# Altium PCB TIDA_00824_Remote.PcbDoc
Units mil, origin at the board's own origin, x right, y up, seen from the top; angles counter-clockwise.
Board outline 140 x 108 mil, 2 copper layers (Top Layer, Bottom Layer), stack 62 mil thick; 1 components, 0 nets, 4 pads, 7 vias.
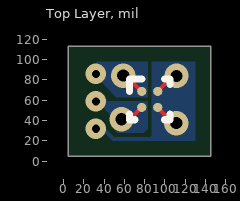
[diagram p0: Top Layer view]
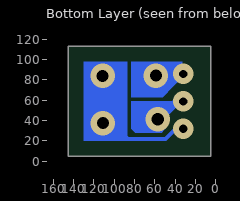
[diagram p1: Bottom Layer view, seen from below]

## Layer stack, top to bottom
Top Layer: signal copper 1.4
Dielectric: core 59.2, FR-4, Dk 4.8
Bottom Layer: signal copper 1.4

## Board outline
5,5 5,113 145,113 145,5

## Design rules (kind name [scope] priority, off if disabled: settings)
AcuteAngle [All] p1: minimum=4.50000000000000E+0001 checktracksonly=FALSE
AssemblyTestPointUsage [All] p1: valid=2
Clearance Clearance_BoardEdge_MountingHoles [OnCopper and InComponentClass('Mounting Holes') vs IsKeepOut] p1: gap=40
Clearance Clearance_BoardEdge_Poly [OnCopper and InPoly vs IsKeepOut] p2: gap=25
Clearance Clearance_BoardEdge [OnCopper and Not InComponentClass('Logo') and not InComponentClass('FiducialMark') and not InRegion(1000,500,4000,800) and Not IsKeepout vs IsKeepOut] p3: gap=75
Clearance Clearance_Poly [InPolygon] p4: gap=25
Clearance [All] p5: gap=7.87
ComponentClearance ComponentClearance_Shunt [InComponentClass('Header') vs InComponentClass('Shunt')] p1: gap=0 collisioncheckmode=3 verticalgap=0 showdistances=FALSE
ComponentClearance ComponentClearance_MountingHoles_FiducialMarks [InComponentClass('Mounting Holes') vs InComponentClass('FiducialMark')] p2: gap=50 collisioncheckmode=3 verticalgap=10 showdistances=FALSE
ComponentClearance ComponentClearance_Logo [InComponentClass('Logo')] p3: gap=50 collisioncheckmode=3 verticalgap=10 showdistances=FALSE
ComponentClearance ComponentClearance_ScrewToNut [(HasFootprint('NY PMS 440 0025 PH')) vs (HasFootprint('Keystone_1902C'))] p4: gap=5 collisioncheckmode=3 verticalgap=10 showdistances=FALSE
ComponentClearance ComponentClearance_MountingHoles [InComponentClass('Mounting Holes')] p5: gap=250 collisioncheckmode=3 verticalgap=100000 showdistances=FALSE
ComponentClearance ComponentClearance_SmallPassives [HasFootprint('0201*') or HasFootprint('0402*') or HasFootprint('0508') or HasFootprint('0603*') or HasFootprint('0612') or HasFootprint('0805*') or HasFootprint('0815*') or HasFootprint('0830*') or HasFootprint('1206*') or HasFootprint('1210*') or HasFootprint('1808*') or HasFootprint('1812*') or HasFootprint('1825*') or HasFootprint('2010*') or HasFootprint('2220*') or HasFootprint('2225*') or HasFootprint('2512*') or HasFootprint('2728*') or HasFootprint('3518*') vs HasFootprint('0201*') or HasFootprint('0402*') or HasFootprint('0508') or HasFootprint('0603*') or HasFootprint('0612') or HasFootprint('0805*') or HasFootprint('0815*') or HasFootprint('0830*') or HasFootprint('1206*') or HasFootprint('1210*') or HasFootprint('1808*') or HasFootprint('1812*') or HasFootprint('1825*') or HasFootprint('2010*') or HasFootprint('2220*') or HasFootprint('2225*') or HasFootprint('2512*') or HasFootprint('2728*') or HasFootprint('3518*')] p6: gap=20 collisioncheckmode=3 verticalgap=10 showdistances=FALSE
ComponentClearance ComponentClearance_THtoSMT [IsThruComponent vs IsSMTComponent] p7: gap=100 collisioncheckmode=3 verticalgap=30 showdistances=FALSE
ComponentClearance ComponentClearance_THtoTH [IsThruComponent vs IsThruComponent] p8: gap=118.11 collisioncheckmode=3 verticalgap=30 showdistances=FALSE
ComponentClearance [All] p9: gap=40 collisioncheckmode=3 verticalgap=10 showdistances=FALSE
DiffPairsRouting [All] p1: maxlimit=100 minlimit=10 mostfreqgap=10 maxuncoupledlength=1000
FabricationTestPointUsage TestPointUsage [All] p1: valid=2 allowmultiple=FALSE
FabricationTestpoint Testpoint [All] p1: side=3 testpointundercomponent=TRUE minsize=40 maxsize=100 preferedsize=60 minholesize=0 maxholesize=40 preferedholesize=32 testpointgrid=1 allowsidetop=TRUE allowsidebottom=TRUE usegrid=TRUE gridtolerance=0.01
FanoutControl Fanout_LCC [IsLCC] p1: bgadir=Out bgaviamode=Centered fanoutstyle=Auto fanoutdirection=Alternating viagrid=1 // Fanout_LCC (Default Rule)
FanoutControl Fanout_BGA [IsBGA] p2: bgadir=Out bgaviamode=Centered fanoutstyle=Auto fanoutdirection=Alternating viagrid=1 // Fanout_BGA (Default Rule)
FanoutControl Fanout_Default [All] p4: bgadir=Out bgaviamode=Centered fanoutstyle=Auto fanoutdirection=Alternating viagrid=1 // Fanout_Default (Default Rule)
FanoutControl Fanout_Small [(CompPinCount < 5)] p5: bgadir=Out bgaviamode=Centered fanoutstyle=Auto fanoutdirection=OutThenIn viagrid=1 // Fanout_Small (Default Rule)
HoleSize [All] p1: absolutevalues=TRUE maxlimit=251 minlimit=4 maxpercent=80.000 minpercent=20.000
MinimumAnnularRing MinimumAnnularRing_ThermalPadVias [IsVia and InAnyComponent] p1: minimumring=3
MinimumAnnularRing [All] p2: minimumring=3
MinimumSolderMaskSliver MinimumSolderMaskSliver_Logo [InComponentClass('Logo') vs InComponentClass('Logo')] p1: minsoldermaskwidth=0.7
MinimumSolderMaskSliver [All] p2: minsoldermaskwidth=3.94
PlaneConnect [All] p1: planeconnectstyle=Relief reliefexpansion=10 reliefentries=4 reliefconductorwidth=10 reliefairgap=10
PolygonConnect [All] p1: connectstyle=Relief reliefconductorwidth=10 reliefentries=4 polygonreliefangle="90 Angle" airgapwidth=10
RoutingVias ThermalPadVias [IsVia and InAnyComponent] p1: holewidth=7.87 width=19.68 viastyle="Through Hole" minholewidth=4 minwidth=8 maxholewidth=12.99 maxwidth=23.62
RoutingVias [All] p2: holewidth=16 width=34 viastyle="Through Hole" minholewidth=7.87 minwidth=24 maxholewidth=40 maxwidth=65
SMDToCorner [All] p1: distance=30000
SilkToSilkClearance SilkToSilkClearance_Pb-FreeLogo [(HasFootprint('Pb-Free_Overlay_Medium') OR HasFootprint('Pb-Free_Overlay_Small')) vs (HasFootprint('Pb-Free_Overlay_Medium') OR HasFootprint('Pb-Free_Overlay_Small'))] p1: silktosilkclearance=0
SilkToSilkClearance [All] p2: silktosilkclearance=5
SilkscreenOverComponentPads [All] p1: minsilkscreentomaskgap=0
SolderMaskExpansion [All] p1: expansion=1.97
Width [All] p1: maxlimit=100 minlimit=4 preferedwidth=4 minimp=50.000000 maximp=50.000000 favimp=50.000000 checkconnectedcopper=TRUE
14 further rules are at their usual default settings.

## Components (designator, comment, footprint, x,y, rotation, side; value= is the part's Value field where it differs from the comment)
U3 "LMT70YFQ" YFQ0004ACAC 85,60.87 r0 top

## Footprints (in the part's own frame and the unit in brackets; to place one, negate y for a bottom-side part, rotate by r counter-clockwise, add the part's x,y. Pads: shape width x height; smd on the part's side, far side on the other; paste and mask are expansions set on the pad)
YFQ0004ACAC [mm] "WCSP, 4-Leads, Body 0.84x0.84mm, Pitch 0.4mm"
  round 0.23 smd paste-0.13 mask+0.038: A1(-0.2,0.2) A2(0.2,0.2) B1(-0.2,-0.2) B2(0.2,-0.2)
  silkscreen extent -0.51,-0.51 0.51,0.51, body extent -0.42,-0.42 0.42,0.42, height 0.58

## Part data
U3: "Precise Temperature Sensor with Output Enable TEMPERATURE SENSOR, YFQ0004ACAC"

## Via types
v1: diameter 24, hole 12, Top Layer to Bottom Layer, 4 vias
v2: diameter 20, hole 8, Top Layer to Bottom Layer, 3 vias

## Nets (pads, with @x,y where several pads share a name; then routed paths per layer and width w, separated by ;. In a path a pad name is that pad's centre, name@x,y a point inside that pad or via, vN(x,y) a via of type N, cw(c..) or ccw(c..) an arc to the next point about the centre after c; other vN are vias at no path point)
pads on no net: U3.A1 U3.A2 U3.B1 U3.B2
copper on no net: | length 195.1
  Top Layer w4: v1@61.44,84.44 77.13,68.75 ; v1@64.06,39.94 77.13,53 ; 92.87,53 v1@109.94,35.94 ; 92.87,68.75 105.13,81 v1@108,81
  Bottom Layer w4: v2@35.87,60 v2@37,60 ; v2@36,36.87 36,35.23 46,25.23 49.34,21.89 80.75,21.89 80.81,21.83 86.35,21.83 95.73,31.22 104.22,31.22 v1@108,35 ; v2@37.13,83 38.13,84 v1@61,84
  other v1: 111.08,37.56 57.19,41.3 58.92,84.27 111.38,84.03
  other v2: 32,32 32,59 32,86

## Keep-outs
Keep-Out Layer:
  lines w1: 482,540 482,0 482,540 ; 482,540 0,540 482,540
  lines w10: 4950,-5 ccw(c4950,0) 4955,0 ; 4950,-5 ccw(c4950,0) 4955,0 ; 4950,-5 ccw(c4950,0) 4955,0 ; 4950,-5 ccw(c4950,0) 4955,0 ; 4950,-5 ccw(c4950,0) 4955,0 ; 4950,-5 ccw(c4950,0) 4955,0
  text ".Layer_Name" at 577,-858.49 h60

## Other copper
Top Layer:
  text ".Layer_Name" at 577,-858.49 h60
Bottom Layer:
  region: 87.11,98 87.11,20 130,20 130,98
  region: 33,98 33,83.36 52,63 83,63 83,98
  region: 43,59 40,64 34.59,57.41 50,42 48.08,34.3 53,28 79.04,28 83,32.12 83,59
  text ".Layer_Name" at 577,-858.49 h60

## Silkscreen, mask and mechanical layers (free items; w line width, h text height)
Top Overlay:
  text ".Layer_Name" at 577,-858.49 h60
Bottom Overlay:
  text ".Layer_Name" at 577,-858.49 h60
Top Paste:
  text ".Layer_Name" at 577,-858.49 h60
Bottom Paste:
  text ".Layer_Name" at 577,-858.49 h60
Top Solder:
  text ".Layer_Name" at 577,-858.49 h60
  text ".Layer_Name" at 577,-858.49 h60
Bottom Solder:
  text ".Layer_Name" at 577,-858.49 h60
Drill Guide:
  text ".Layer_Name" at 577,-858.49 h60
M1 Board Outline:
  the board outline again, w20
  text ".Layer_Name" at 577,-858.49 h60
M2 Board Dimensions:
  rectangle: 0,-285.5 125,-160.5
  rectangle: 125,-410.5 500,-285.5
  lines w7: 0,-285.5 1000,-285.5 ; 125,-410.5 125,-160.5 ; 250,-410.5 250,-160.5 ; 500,-410.5 500,-160.5 ; 750,-410.5 750,-160.5 ; 0,-410.5 1000,-410.5 1000,-160.5 0,-160.5 0,-410.5
  text ".Layer_Name" at 577,-858.49 h60
M3 3D STEP Top:
  text ".Layer_Name" at 577,-858.49 h60
M4 3D STEP Bottom:
  text ".Layer_Name" at 577,-858.49 h60
M5 Assembly Top:
  lines w10: -292,-930.17 6308,-930.17 ; -292,-726.83 6310,-726.83 ; -292,-523.5 -292,-1133.5 3713,-1133.5 6310,-1133.5 6310,-523.5 -291.5,-523.5 -291.5,-1133.5 1284,-1133.5 ; 2173,-1133.5 2173,-523.5 ; 3440,-726.83 3440,-523.5 ; 4280,-726.83 4280,-523.5 ; 4902,-1140 4902,-937.17
  text "COMPONENTS MARKED 'DNP' SHOULD NOT BE POPULATED." at 1153.5,-318.5 h60
  text "ASSEMBLY VARIANT:" at 1153,-434 h60
  text ".VariantName" at 2189,-434 h60
  text "PCB VIEWED FROM TOP SIDE" at -228.5,-655.67 h60
  text "BOARD #:" at 2248,-655.67 h60
  text ".PRJ_Number" at 2793.5,-655.67 h60
  text "REV:" at 3638,-655.67 h60
  text ".PCB_Rev" at 3929.5,-655.67 h60
  text "SVN REV:" at 4476,-655.67 h60
  text ".VersionControl_RevNumber" at 4982,-655.67 h60
  text "IGNORE ->" at -228.5,-858.49 h60
  text "PLOT NAME =" at -228.5,-1064.34 h60
  text ".plot_File_Name" at 577,-1064.34 h60
  text "GENERATED    :" at 2250,-1064.34 h60
  text ".Print_Date" at 3119.5,-1064.34 h60
  text ".Print_Time" at 3848.5,-1064.34 h60
  text "TEXAS INSTRUMENTS" at 5113,-1064.34 h60
M6 Assembly Bottom:
  lines w10: -292.5,-727.33 6309.5,-727.33 ; -290.5,-930.67 6309.5,-930.67 ; 1115.5,-1140.5 1115.5,-937.67 ; 1737.5,-727.33 1737.5,-524 ; 2577.5,-727.33 2577.5,-524 ; 3844.5,-1134 3844.5,-524 ; 4733.5,-1134 6309,-1134 6309,-524 -292.5,-524 -292.5,-1134 2304.5,-1134 6309.5,-1134 6309.5,-524
  text "COMPONENTS MARKED 'DNP' SHOULD NOT BE POPULATED." at 6102,-318 h60
  text ".VariantName" at 5058,-434 h60
  text "ASSEMBLY VARIANT:" at 6097,-434 h60
  text ".VersionControl_RevNumber" at 1035.5,-656.17 h60
  text "SVN REV:" at 1541.5,-656.17 h60
  text ".PCB_Rev" at 2088,-656.17 h60
  text "REV:" at 2379.5,-656.17 h60
  text ".PRJ_Number" at 3224,-656.17 h60
  text "BOARD #:" at 3769.5,-656.17 h60
  text "PCB VIEWED FROM BOTTOM SIDE" at 6246,-656.17 h60
  text "IGNORE ->" at 2547.85,-858.49 h60
  text "TEXAS INSTRUMENTS" at 904.5,-1064.84 h60
  text ".Print_Time" at 2169,-1064.84 h60
  text ".Print_Date" at 2898,-1064.84 h60
  text "GENERATED    :" at 3767.5,-1064.84 h60
  text ".plot_File_Name" at 5440.5,-1064.84 h60
  text "PLOT NAME =" at 6246,-1064.84 h60
M9 Title Sheet:
  drawing of 57 lines, arcs and shapes, not listed
  text "1" at 739.84,8036.5 h70
  text "2" at 3235.5,8036.5 h70
  text "3" at 5724.84,8036.5 h70
  text "4" at 8231.51,8036.5 h70
  text "5" at 10730.5,8036.5 h70
  text "6" at 13235.5,8036.5 h70
  text "A" at -416.5,6893.5 h70
  text "A" at 14383.5,6893.5 h70
  text "B" at -416.5,4513.5 h70
  text "B" at 14383.5,4513.5 h70
  text "C" at -416.5,2138.5 h70
  text "C" at 14383.5,2138.5 h70
  text "PROJECT TITLE:" at 11343.5,277.5 h45
  text ".PRJ_Title" at 11393.5,144.17 h70
  text "DESIGNED FOR:" at 11343.5,-23.5 h45
  text ".PRJ_Customer" at 11393.5,-163.5 h70
  text "D" at -416.5,-231.5 h70
  text "D" at 14383.5,-231.5 h70
  text "FILE NAME:" at 11343.5,-323.5 h45
  text ".PCB_File_Name_No_Path" at 11393.5,-443.5 h70
  text "Texas Instruments (TI) and/or its licensors do not warrant the accuracy or completeness of this specification" at 6374,-605.34 h45
  text "ENGINEER:" at 11343.5,-613.5 h45
  text "LAYOUT BY:" at 12848.5,-613.5 h45
  text "or any information contained therein. TI and/or its licensors do not warrant that this design will meet" at 6329.01,-718 h45
  text ".PRJ_Engineer" at 11393.5,-768.49 h70
  text ".PCB_Layout" at 12899,-768.49 h70
  text "the specifications, will be suitable for your application or fit for any particular purpose, or will operate in" at 6329.01,-830.67 h45
  text ".Layer_Name" at 577,-858.49 h60
  text "ALTIUM DESIGNER VERSION:" at 12848.5,-923.5 h45
  text "an implementation. TI and/or its licensors do not warrant that the design is production worthy. You should" at 6329.01,-943.33 h45
  text "completely validate and test your design implementation to confirm the system functionality for your application." at 6374,-1056 h45
  text ".print_Scale" at 11393.5,-1056.83 h70
  text ".Application_BuildNumber" at 12899,-1056.83 h70
  text "1" at 739.84,-1263.5 h70
  text "2" at 3235.5,-1263.5 h70
  text "3" at 5724.84,-1263.5 h70
  text "4" at 8231.51,-1263.5 h70
  text "5" at 10730.5,-1263.5 h70
  text "6" at 13235.5,-1263.5 h70
M10 Fab Notes:
  drawing of 185 lines, arcs and shapes, not listed
  text "DESIGN INFORMATION" at 12381.02,5910 h60
  text "MIN. TRACK WIDTH:" at 11736.46,5730 h60
  text "4" at 12832.7,5730 h60
  text "MIL" at 12987.46,5730 h60
  text "MIN. CLEARANCE:" at 11736.46,5598 h60
  text "0.2" at 12772.7,5598 h60
  text "mm" at 12987.46,5598 h60
  text "14" at 12808,5482 h60
  text "MIN. VIA PAD SIZE:" at 11736.46,5466 h60
  text "MIL" at 12987.46,5466 h60
  text "0.05mm (2MIL)" at 12431.46,5324.29 h60
  text "MINIMUM ANNULAR RING" at 11407.23,5320 h60
  text "EXTERNAL" at 13139.46,5320 h60
  text "PER" at 11607.23,5202 h60
  text "IPC-D-275 CLASS 2 LEVEL C" at 11827.23,5202 h60
  text "MIL, HOLES" at 13315.46,5089.71 h60
  text "+/-" at 12923,5089 h60
  text "+/-" at 13777,5089 h60
  text "REGISTRATION TOLERANCES:" at 11407.23,5084 h60
  text "METAL" at 12607,5084 h60
  text "5" at 13183.2,5084 h60
  text "3" at 14016.2,5084 h60
  text "MIL" at 14132.46,5084 h60
  text "MATERIAL: (UL94V-0 Compliant)" at 11332.46,4874.54 h60
  text "FR-4 High Tg" at 12318.9,4734.21 h60
  text "FR-408" at 11753.46,4725.64 h60
  text "X" at 12165.46,4725.64 h60
  text "OTHER" at 13241.46,4725.64 h60
  text "20 MIL" at 13706,4598 h60
  text "62 MIL (1.6mm) +/-10%" at 12073.56,4562.92 h60
  text "THICKNESS:" at 11407.23,4558.64 h60
  text "OTHER" at 13358.46,4558.64 h60
  text "X" at 13237.4,4554.64 h60
  text "TOLERANCE:" at 11407.23,4400.64 h60
  text "X" at 12246.53,4400.64 h60
  text "ANSI IPC-6012 TYPE 3 CLASS 2" at 12433.48,4400.64 h60
  text "OTHER +/-" at 12433.46,4244.64 h60
  text "BOW & TWIST:" at 11407.23,4087.64 h60
  text "X" at 12246.53,4087.64 h60
  text "ANSI IPC-6012 TYPE 3 CLASS 2" at 12433.48,4087.64 h60
  text "OTHER +/-" at 12433.46,3929.13 h60
  text "DRILLING:" at 11332.46,3790.64 h60
  text "REFERENCE:" at 11407.23,3673.64 h60
  text "X" at 12055.46,3673.64 h60
  text "AS SHOWN" at 12242.46,3673.64 h60
  text "X" at 12956.46,3673.64 h60
  text "NC_DRILL FILES" at 13093.46,3673.64 h60
  text "PTH MIN COPPER THICKNESS:" at 11407.23,3515.64 h60
  text "X" at 12757.46,3515.64 h60
  text "1MIL" at 12894.46,3515.64 h60
  text "OTHER" at 13391.46,3515.64 h60
  text "BOARD FINISH:" at 11332.46,3356.64 h60
  text "SILKSCREEN:" at 11487.68,3238.64 h60
  text "X" at 12436.46,3238.64 h60
  text "TOP" at 12562.46,3238.64 h60
  text "BOTTOM" at 13073.46,3238.64 h60
  text "SILKSCREEN COLOR:" at 11487.68,3071.64 h60
  text "X" at 12435.42,3071.64 h60
  text "WHITE" at 12562.46,3071.64 h60
  text "OTHER" at 13073.46,3071.64 h60
  text "SOLDER RESIST COLOR:" at 11487.68,2901.64 h60
  text "X" at 12055.42,2742.44 h60
  text "GREEN" at 12182.46,2742.44 h60
  text "BLUE" at 12773.46,2742.44 h60
  text "OTHER" at 13311.46,2742.44 h60
  text "IMMERSION GOLD (ENIG)" at 12393.46,2553.92 h60
  text "ENEPIG" at 13731,2550.64 h60
  text "SURFACE FINISH:" at 11332.46,2549.64 h60
  text "X" at 12206.51,2549.64 h60
  text "IMM. TIN/SILVER OR EQUIV" at 11662,2392.64 h60
  text "OTHER" at 13093.46,2392.64 h60
  text "ARRAY/PANEL:" at 11332.46,2213.64 h60
  text "CUT AND TRIM PER MECH LAYER 1" at 12393.46,2209.35 h60
  text "N.C. ROUTE" at 12393.46,2057.64 h60
  text "X" at 13072.46,2057.64 h60
  text "V. SCORE" at 13259.46,2057.64 h60
  text "CERTIFICATION:" at 11332.46,1920.64 h60
  text "MATERIALS AND WORKMANSHIP FOR ALL PCBS" at 12057.46,1920.64 h60
  text "TO MEET OR EXCEED THE REQUIREMENTS OF:" at 12057.46,1822.64 h60
  text "X" at 11683.96,1686.13 h60
  text "ANSI IPC-A-600F CLASS ->" at 11822.96,1686.13 h60
  text "X" at 13462.02,1686.13 h60
  text "2" at 13580.96,1686.14 h60
  text "1" at 13265.96,1684.64 h60
  text "3" at 13934.96,1684.64 h60
  text "X" at 11686.02,1526.64 h60
  text "UL 94V-0" at 11822.96,1526.64 h60
  text "X" at 12498.02,1526.64 h60
  text "RoHS" at 12634.96,1526.64 h60
  text "OTHER" at 13279.36,1526.64 h60
  text "PER ORDER" at 13676.42,1526.64 h60
  text "ADDITIONAL REQUIREMENTS:" at 11332.46,1385.64 h60
  text "MICROSECTION:" at 11407.23,1270.64 h60
  text "YES" at 12312.96,1270.64 h60
  text "REQUIRED" at 13174.46,1114.49 h60
  text "BARE BOARD ELEC. TEST:" at 11407.23,1111.64 h60
  text "NONE" at 12712.96,1111.64 h60
  text "X" at 13047.46,1111.64 h60
  text "PER ORDER" at 13766.46,1111.64 h60
  text "MANUFACTURER'S UL:" at 11407.23,954.64 h60
  text "RAIL" at 12572.96,950.35 h60
  text "METAL" at 13064.77,950.35 h60
  text "X" at 13440,950 h60
  text "SILK" at 13576.46,950.35 h60
  text ".Layer_Name" at 577,-858.49 h60
M11 Gerber Information:
  lines w10: -292,-930.17 6308,-930.17 ; -292,-726.83 6310,-726.83 ; -292,-523.5 -292,-1133.5 3713,-1133.5 6310,-1133.5 6310,-523.5 -291.5,-523.5 -291.5,-1133.5 1284,-1133.5 ; 2173,-1133.5 2173,-523.5 ; 3440,-726.83 3440,-523.5 ; 4280,-726.83 4280,-523.5 ; 4902,-1140 4902,-937.17
  text "ALL ARTWORK VIEWED FROM TOP SIDE" at -228.5,-655.67 h60
  text "BOARD #:" at 2248,-655.67 h60
  text ".PRJ_Number" at 2793.5,-655.67 h60
  text "REV:" at 3638,-655.67 h60
  text ".PCB_Rev" at 3929.5,-655.67 h60
  text "SVN REV:" at 4476,-655.67 h60
  text ".VersionControl_RevNumber" at 4982,-655.67 h60
  text "LAYER NAME =" at -228.5,-858.49 h60
  text "PLOT NAME =" at -228.5,-1064.34 h60
  text ".plot_File_Name" at 577,-1064.34 h60
  text "GENERATED    :" at 2250,-1064.34 h60
  text ".Print_Date" at 3119.5,-1064.34 h60
  text ".Print_Time" at 3848.5,-1064.34 h60
  text "TEXAS INSTRUMENTS" at 5113,-1064.34 h60
M12 Stackup:
  lines w6: 11360,7460 13910,7460 ; 11360,7564.4 13910,7564.4 ; 11300,6975 ccw(c11334,6975) 11334,6941 13936,6941 ccw(c13936,6975) 13970,6975 13970,7681 ccw(c13936,7681) 13936,7715 11334,7715 ccw(c11334,7681) 11300,7681 11300,6975
  text "The Stackup Legend below this is static." at 11605.5,7874.5 h60
  text "If you change the stackup, update the Legend." at 11615.5,7784.5 h60
  text "Layer Stack Up Detail for: Ref_Design.PcbDoc" at 11360,7597.1 h57
  text "Layer" at 11360,7525.4 h24
  text "Gerber" at 12255.81,7525.4 h24
  text "Copper" at 12819.33,7525.4 h24
  text "Dielectric" at 13422.04,7525.4 h24
  text "Name" at 11360,7477.4 h24
  text "Document" at 12255.81,7477.4 h24
  text "Thickness" at 12819.33,7477.4 h24
  text "Material" at 13422.04,7477.4 h24
  text "Top Solder Mask" at 11360,7384.44 h34
  text "(.GTS)" at 12255.81,7384.44 h34
  text "Solder Resist" at 13422.04,7384.44 h34
  text "Top Layer" at 11360,7287.69 h34
  text "(.GTL)" at 12255.81,7287.69 h34
  text "1.4mil" at 12819.33,7287.69 h34
  text "FR-4 20 MIL THICK" at 13422.04,7239.31 h34
  text "Bottom Layer" at 11360,7190.94 h34
  text "(.GBL)" at 12255.81,7190.94 h34
  text "1.4mil" at 12819.33,7190.94 h34
  text "Bottom Solder Mask" at 11360,7094.19 h34
  text "(.GBS)" at 12255.81,7094.19 h34
  text "No Solder Resist" at 13422.04,7094.19 h34
  text ".Layer_Name" at 577,-858.49 h60
M13 Component Bodies Top:
  text ".Layer_Name" at 577,-858.49 h60
M14 Component Bodies Bottom:
  text ".Layer_Name" at 577,-858.49 h60
M15 Courtyards Top:
  text ".Layer_Name" at 577,-858.49 h60
M16 Courtyards Bottom:
  text ".Layer_Name" at 577,-858.49 h60
Drill Drawing:
  text ".legend" at 5122.5,725.5 h60
  text "Drill Table" at 5147.5,540.5 h60
  text ".Layer_Name" at 577,-858.49 h60

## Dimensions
0,0 to 145,5 on M2 Board Dimensions
0,0 to 5,113 on M2 Board Dimensions
0,-410.5 to 1000,-410.5 on M2 Board Dimensions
